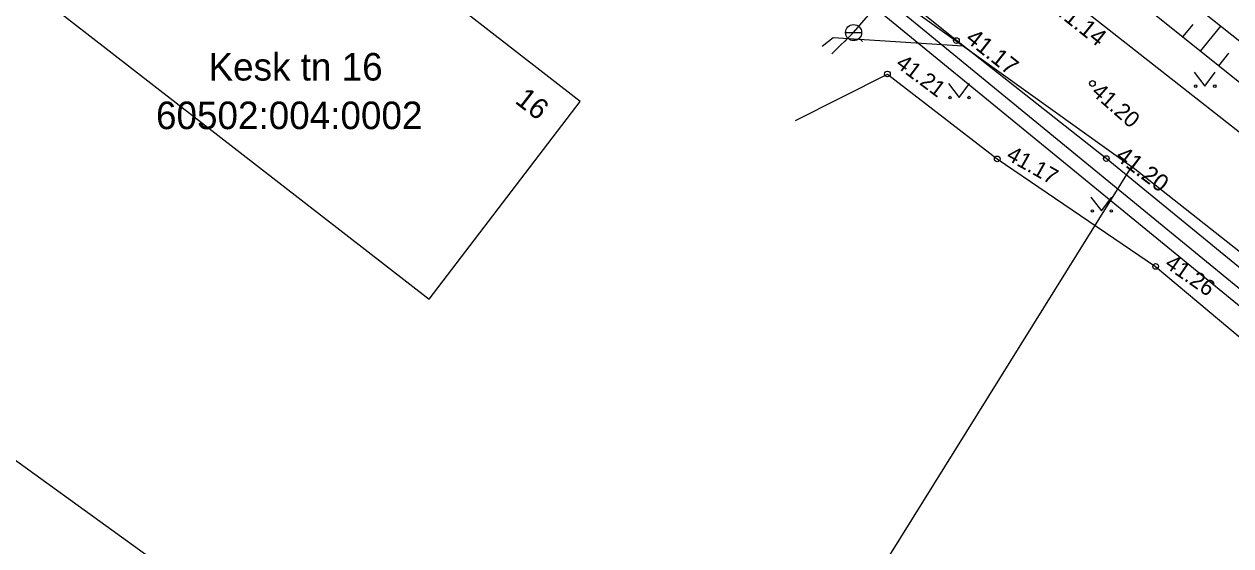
# Model space of a CAD drawing. Extents: x 641898 to 642452, y 6471715 to 6472255.
# Drawn here: x 642071.4 to 642124, y 6471973.9 to 6471996.6 of the extents above; entities that cross this region are included whole.
import ezdxf

# ---------------------------------------------------------------- set-up
doc = ezdxf.new("R2010")
doc.units = 0
for name, color, linetype in [('HALJASTUS', 7, 'Continuous'), ('HOONE', 7, 'Continuous'), ('KORGUS-EH2000', 7, 'Continuous'), ('KTRASS', 7, 'Continuous'), ('PIIR', 7, 'Continuous'), ('RELJEEF', 7, 'Continuous'), ('TEE', 7, 'Continuous'), ('VKAEV', 7, 'Continuous'), ('VTRASS', 7, 'Continuous')]:
    doc.layers.add(name, color=color, linetype=linetype)

msp = doc.modelspace()

# ---------------------------------------------------------------- linework, layer by layer
at = {"layer": 'HALJASTUS'}
for p, q in [((642122.389, 6471994.548), (642122.853, 6471993.941)), ((642122.853, 6471993.941), (642123.298, 6471994.548)), ((642111.692, 6471994.048), (642112.156, 6471993.442)), ((642112.156, 6471993.442), (642112.601, 6471994.048)), ((642117.888, 6471989.112), (642118.352, 6471988.505)), ((642118.352, 6471988.505), (642118.797, 6471989.112))]:
    msp.add_line(p, q, dxfattribs=at)
msp.add_lwpolyline([(642105.033, 6471992.439), (642109.028, 6471994.468), (642113.809, 6471990.771), (642120.708, 6471986.089), (642127.178, 6471980.654)], dxfattribs=at)
for centre in [(642122.452, 6471993.941), (642123.281, 6471993.941), (642111.755, 6471993.442), (642112.583, 6471993.442), (642117.951, 6471988.505), (642118.779, 6471988.505)]:
    msp.add_circle(centre, 0.055, dxfattribs=at)
at = {"layer": 'HOONE'}
msp.add_lwpolyline([(642065.09, 6472003.293), (642089.074, 6471984.663), (642095.654, 6471993.274), (642071.669, 6472011.904), (642065.09, 6472003.293)], dxfattribs=at)
at = {"layer": 'KORGUS-EH2000'}
for centre in [(642112.034, 6471995.922), (642109.028, 6471994.468), (642117.956, 6471994.055), (642113.809, 6471990.771), (642118.56, 6471990.787), (642120.708, 6471986.089)]:
    msp.add_circle(centre, 0.125, dxfattribs=at)
at = {"layer": 'KTRASS'}
msp.add_lwpolyline([(642136.804, 6471974.904), (642101.491, 6472003.87)], dxfattribs=at)
at = {"layer": 'PIIR'}
for p, q in [((642068.76, 6472026.95), (642119.65, 6471990.44)), ((642085.554, 6471967.183), (642045.38, 6471996.16)), ((642119.65, 6471990.44), (642100.887, 6471960.305)), ((642149.07, 6471967.26), (642119.65, 6471990.44))]:
    msp.add_line(p, q, dxfattribs=at)
at = {"layer": 'RELJEEF'}
for p, q in [((642122.321, 6471996.63), (642121.881, 6471996.081)), ((642122.662, 6471995.456), (642123.543, 6471996.557)), ((642123.884, 6471995.383), (642123.442, 6471994.831))]:
    msp.add_line(p, q, dxfattribs=at)
msp.add_lwpolyline([(642146.331, 6471977.025), (642136.065, 6471984.84), (642127.477, 6471991.602), (642117.617, 6471999.493), (642106.697, 6472008.186)], dxfattribs=at)
at = {"layer": 'TEE'}
for points in [[(642127.755, 6471983.25), (642118.56, 6471990.787), (642112.034, 6471995.922), (642104.507, 6472001.966), (642102.538, 6472003.592), (642099.411, 6472006.017), (642092.935, 6472011.037), (642082.111, 6472019.423), (642074.673, 6472025.315), (642072.485, 6472026.831), (642072.011, 6472026.035), (642071.166, 6472026.263), (642070.297, 6472026.346), (642067.3, 6472026.288), (642064.299, 6472028.73), (642063.954, 6472029.272), (642061.62, 6472031.153), (642060.293, 6472030.111), (642058.489, 6472031.665), (642056.171, 6472033.433), (642056.198, 6472033.468), (642053.173, 6472035.891), (642052.964, 6472035.998), (642047.466, 6472040.459)], [(642131.75, 6471990.028), (642121.917, 6471997.85), (642113.172, 6472004.818), (642110.49, 6472007.053), (642106.954, 6472009.482)], [(642116.8, 6471997.886), (642127.037, 6471989.838)], [(642106.184, 6471995.674), (642106.671, 6471996.052), (642112.318, 6471995.698)]]:
    msp.add_lwpolyline(points, dxfattribs=at)
at = {"layer": 'VKAEV'}
for p, q in [((642107.31, 6471996.025), (642107.17, 6471995.885)), ((642107.207, 6471996.272), (642107.907, 6471996.272)), ((642107.804, 6471996.025), (642107.944, 6471995.885))]:
    msp.add_line(p, q, dxfattribs=at)
msp.add_circle((642107.557, 6471996.272), 0.35, dxfattribs=at)
at = {"layer": 'VTRASS'}
for points in [[(642131.146, 6471978.791), (642122.669, 6471985.738), (642108.487, 6471997.357), (642100.73, 6472003.718), (642086.367, 6472014.732), (642072.004, 6472025.747), (642070.54, 6472026.319), (642063.386, 6472027.837), (642057.563, 6472020.38), (642046.398, 6472006.083), (642029.41, 6471984.33), (642022.753, 6471976.477), (642013.331, 6471964.779), (642003.99, 6471953.421), (641999.884, 6471948.226), (641984.12, 6471925.503), (641973.431, 6471931.653), (641967.433, 6471935.11)], [(642106.612, 6471995.349), (642107.557, 6471996.272), (642108.487, 6471997.357)]]:
    msp.add_lwpolyline(points, dxfattribs=at)

# ---------------------------------------------------------------- texts
at = {"layer": 'HOONE'}
msp.add_text('16', height=0.9, rotation=322.1611, dxfattribs=at).set_placement((642092.769, 6471993.238))
at = {"layer": 'KORGUS-EH2000'}
for s, height, rotation, p in [('41.14', 0.75, 321.5154, (642116.22, 6471997.193)), ('41.17', 0.75, 321.6158, (642112.384, 6471995.922)), ('41.21', 0.7, 323.2123, (642109.344, 6471994.821)), ('41.20', 0.7, 318.6574, (642117.87, 6471993.618)), ('41.17', 0.7, 330.5913, (642114.159, 6471990.771)), ('41.20', 0.75, 323.0447, (642118.91, 6471990.787)), ('41.26', 0.7, 325.2466, (642121.058, 6471986.089))]:
    msp.add_text(s, height=height, rotation=rotation, dxfattribs=at).set_placement(p)
at = {"layer": 'PIIR'}
for s, p in [('Kesk tn 16', (642079.47, 6471994.184)), ('60502:004:0002', (642077.183, 6471992.068))]:
    msp.add_text(s, height=1.2, dxfattribs=at).set_placement(p)

doc.saveas('drawing.dxf')
